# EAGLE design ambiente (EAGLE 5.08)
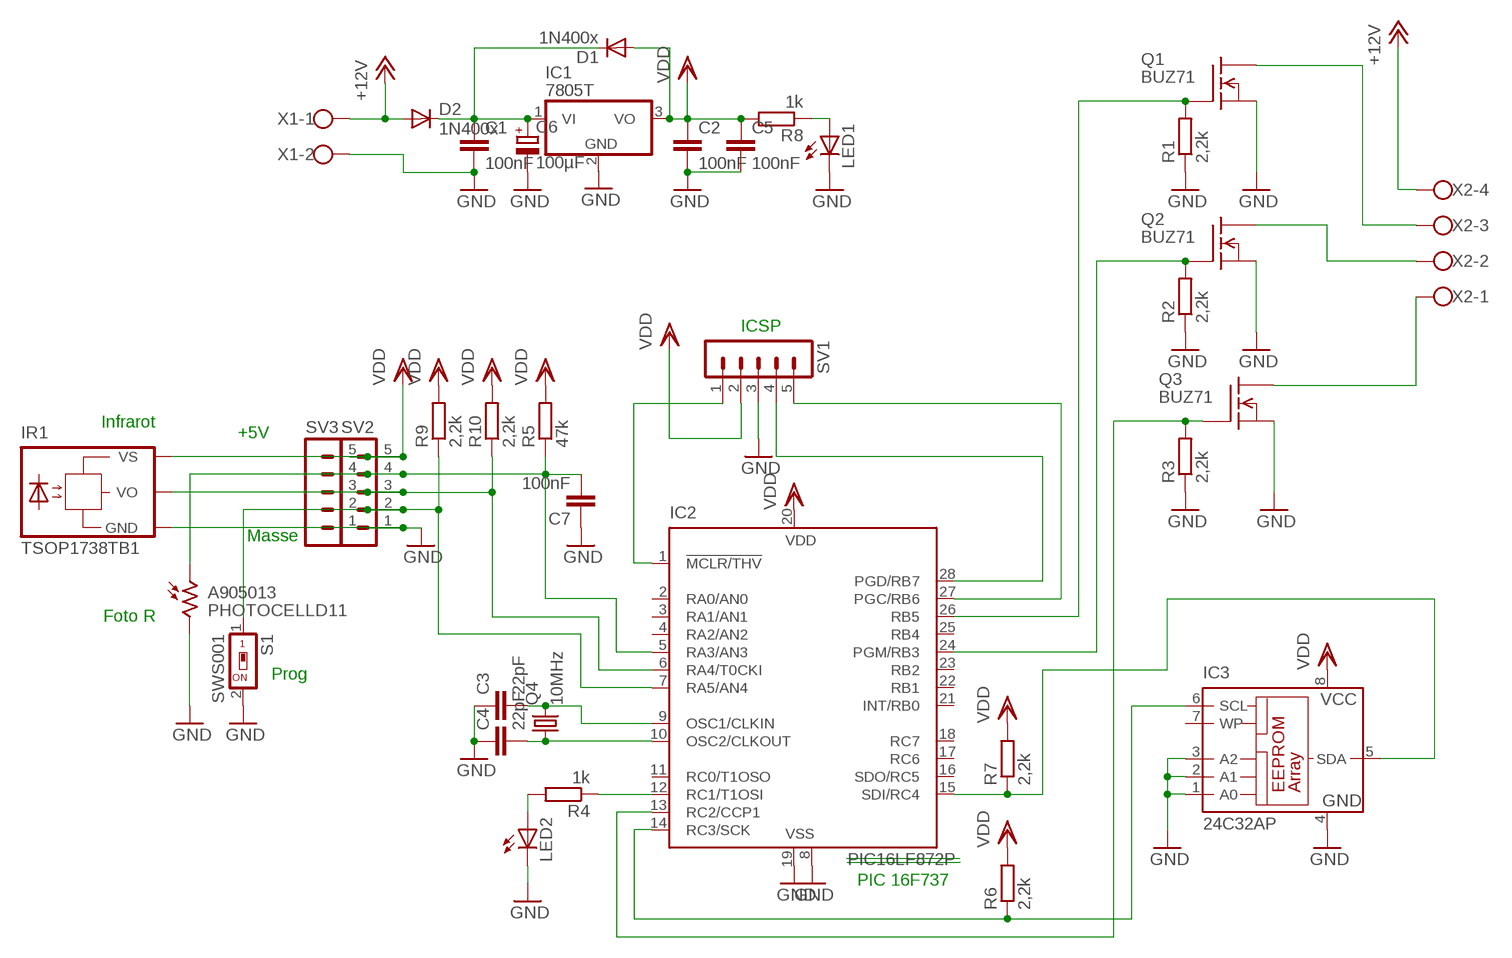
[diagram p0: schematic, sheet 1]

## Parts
A905013  PHOTOCELLD11  [D11XX_H]
C1  100nF  C-EUC1206K  [C1206K]
C2  100nF  C-EUC1206K  [C1206K]
C3  22pF  C-EUC1206K  [C1206K]
C4  22pF  C-EUC1206K  [C1206K]
C5  100nF  C-EUC1206K  [C1206K]
C6  100µF  CPOL-EUE5-10.5  [E5-10,5]
C7  100nF  C-EUC1206K  [C1206K]
D1  1N400x  DIODE-SMC  [SMC]
D2  1N400x  DIODE-SMC  [SMC]
IC1  7805T  [TO220H]
IC2  PIC16LF872P  [DIL28-3]
IC3  24C32AP  [DIL8]
IR1  TSOP1738TB1  [TSOP17_TB1]
LED1  LED3MM  [LED3MM]
LED2  LED3MM  [LED3MM]
Q1  BUZ71  [TO220]
Q2  BUZ71  [TO220]
Q3  BUZ71  [TO220]
Q4  10MHz  CRYSTALHC49S  [HC49/S]
R1  2,2k  R-EU_R1206  [R1206]
R2  2,2k  R-EU_R1206  [R1206]
R3  2,2k  R-EU_R1206  [R1206]
R4  1k  R-EU_R1206  [R1206]
R5  47k  R-EU_R1206  [R1206]
R6  2,2k  R-EU_R1206  [R1206]
R7  2,2k  R-EU_R1206  [R1206]
R8  1k  R-EU_R1206  [R1206]
R9  2,2k  R-EU_R1206  [R1206]
R10  2,2k  R-EU_R1206  [R1206]
S1  SWS001  [SMS-001]
SV1  MA05-1  [MA05-1]
SV2  MA05-1  [MA05-1]
SV3  MA05-1  [MA05-1]
X1  W237-102  [W237-102]
X2  W237-4  [W237-4]

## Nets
+12V: D2.A X1.1 X2.4
GND: A905013.2 C1.2 C2.2 C3.1 C4.1 C5.2 C6.- C7.1 IC1.2(GND) IC2.8(VSS) IC2.19(VSS) IC3.1(A0) IC3.2(A1) IC3.3(A2) IC3.4(GND) IR1.GND LED1.K(C) LED2.K(C) Q1.3(S) Q2.3(S) Q3.3(S) R1.1 R2.1 R3.1 S1.2 SV1.3 SV2.1 SV3.1 X1.2
N$1: C1.1 C6.+ D1.C D2.C IC1.1(VI)
N$2: Q1.2(D) X2.3
N$3: Q2.2(D) X2.2
N$4: Q3.2(D) X2.1
N$5: IC2.13(RC2/CCP1) Q3.1(G) R3.2
N$6: IC2.24(PGM/RB3) Q2.1(G) R2.2
N$7: IC2.26(RB5) Q1.1(G) R1.2
N$8: C3.2 IC2.9(OSC1/CLKIN) Q4.2
N$9: C4.2 IC2.10(OSC2/CLKOUT) Q4.1
N$10: A905013.1 C7.2 IC2.5(RA3/AN3) R5.1 SV2.4 SV3.4
N$11: IC2.1(!MCLR/THV) SV1.1
N$12: IC2.28(PGD/RB7) SV1.4
N$13: IC2.27(PGC/RB6) SV1.5
N$14: IC2.6(RA4/T0CKI) IR1.VO R10.1 SV2.3 SV3.3
N$15: IC2.7(RA5/AN4) R9.1 S1.1 SV2.2 SV3.2
N$21: LED1.A R8.1
N$24: IC2.12(RC1/T1OSI) R4.1
N$32: IC2.14(RC3/SCK) IC3.6(SCL) R6.1
N$34: IC2.15(SDI/RC4) IC3.5(SDA) R7.1
N$35: LED2.A R4.2
VDD: C2.1 C5.1 D1.A IC1.3(VO) IC2.20(VDD) IC3.8(VCC) IR1.VS R5.2 R6.2 R7.2 R8.2 R9.2 R10.2 SV1.2 SV2.5 SV3.5
Unconnected: IC2.2(RA0/AN0) IC2.3(RA1/AN1) IC2.4(RA2/AN2) IC2.11(RC0/T1OSO) IC2.16(SDO/RC5) IC2.17(RC6) IC2.18(RC7) IC2.21(INT/RB0) IC2.22(RB1) IC2.23(RB2) IC2.25(RB4) IC3.7(WP)

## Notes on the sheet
- ICSP
- Infrarot
- +5V
- Masse
- Foto R
- Prog
- PIC 16F737

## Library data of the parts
A905013 = photo-elements:PHOTOCELL: Photo Sensor
C1-C5 C7 = rcl:C-EU: CAPACITOR, European symbol
C6 = rcl:CPOL-EU: POLARIZED CAPACITOR, European symbol
D1 D2 = diode:DIODE-: DIODE
IC1 = linear:78*: Positive VOLTAGE REGULATOR Source: http://cache.national.com/ds/LM/LM78L05.pdf http://www.fairchildsemi.com/ds/LM/LM7805.pdf
IC2 = microchip:PIC16*872: MICROCONTROLLER flash type
IC3 = microchip:24*: Serial EEPROM I2C
IR1 = telefunken:TSOP17*TB1: TSOP17..TB1 IR Receiver Modules for Remote Control Systems Source: http://www.vishay.com/docs/82042/82042.pdf
LED1 LED2 = led:LED: LED
Q1-Q3 = transistor-fet:BUZ71: N-Channel Enhancement MOSFET 50V; 14A; 0,1Ohm
Q4 = crystal:CRYSTAL: CRYSTAL
R1-R10 = rcl:R-EU_: RESISTOR, European symbol
S1 = smd-special:SWS001: SMD Dip Switch 1 pol.
SV1-SV3 = con-lstb:MA05-1: PIN HEADER
X1 = con-wago-500:W237-102: WAGO SCREW CLAMP
X2 = con-wago-500:W237-4: WAGO SCREW CLAMP

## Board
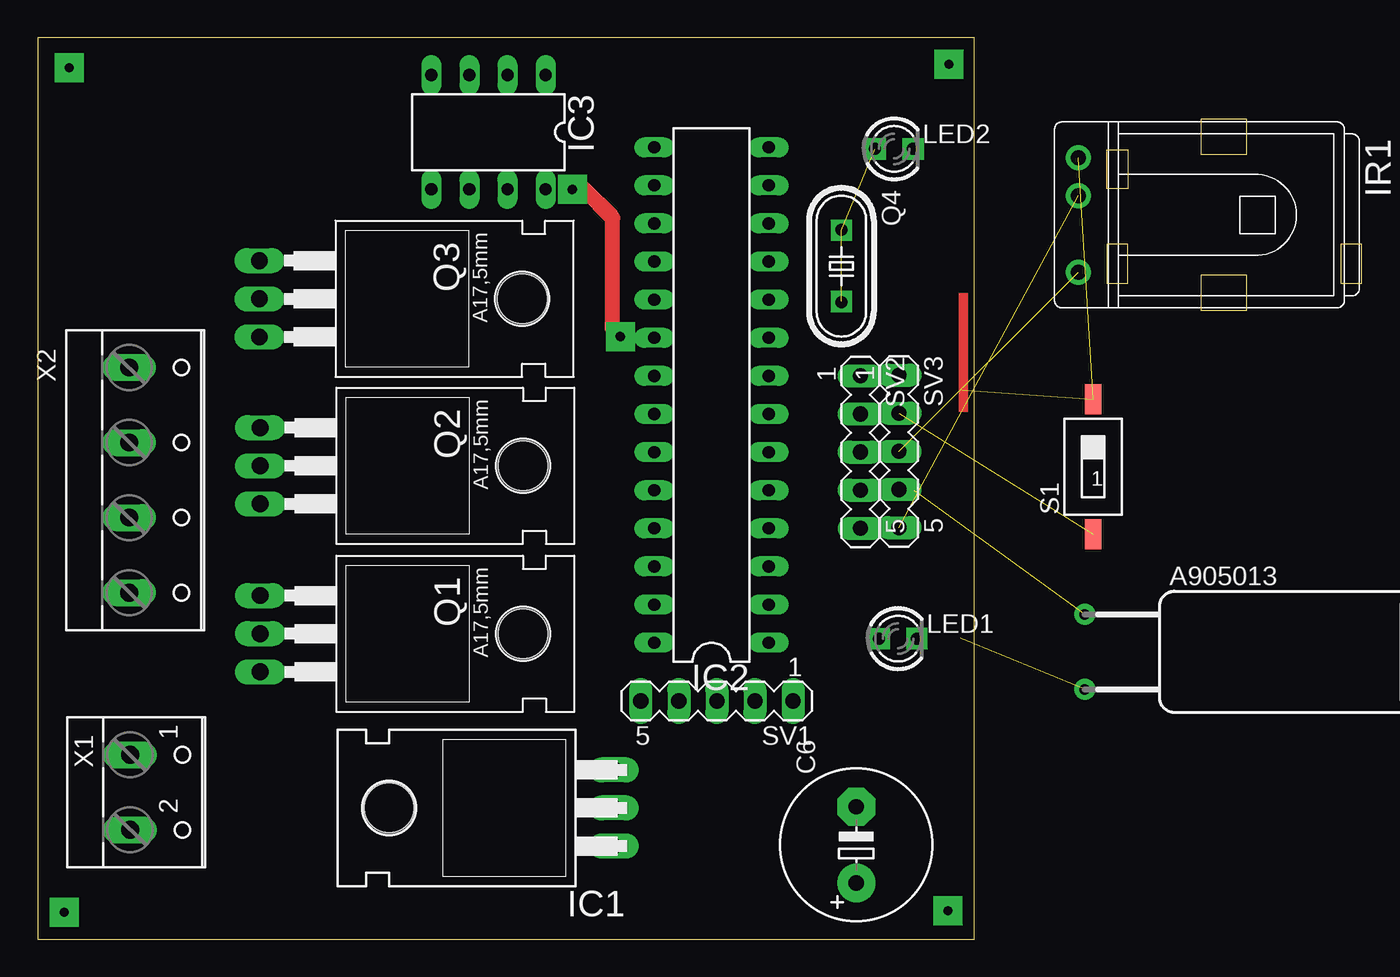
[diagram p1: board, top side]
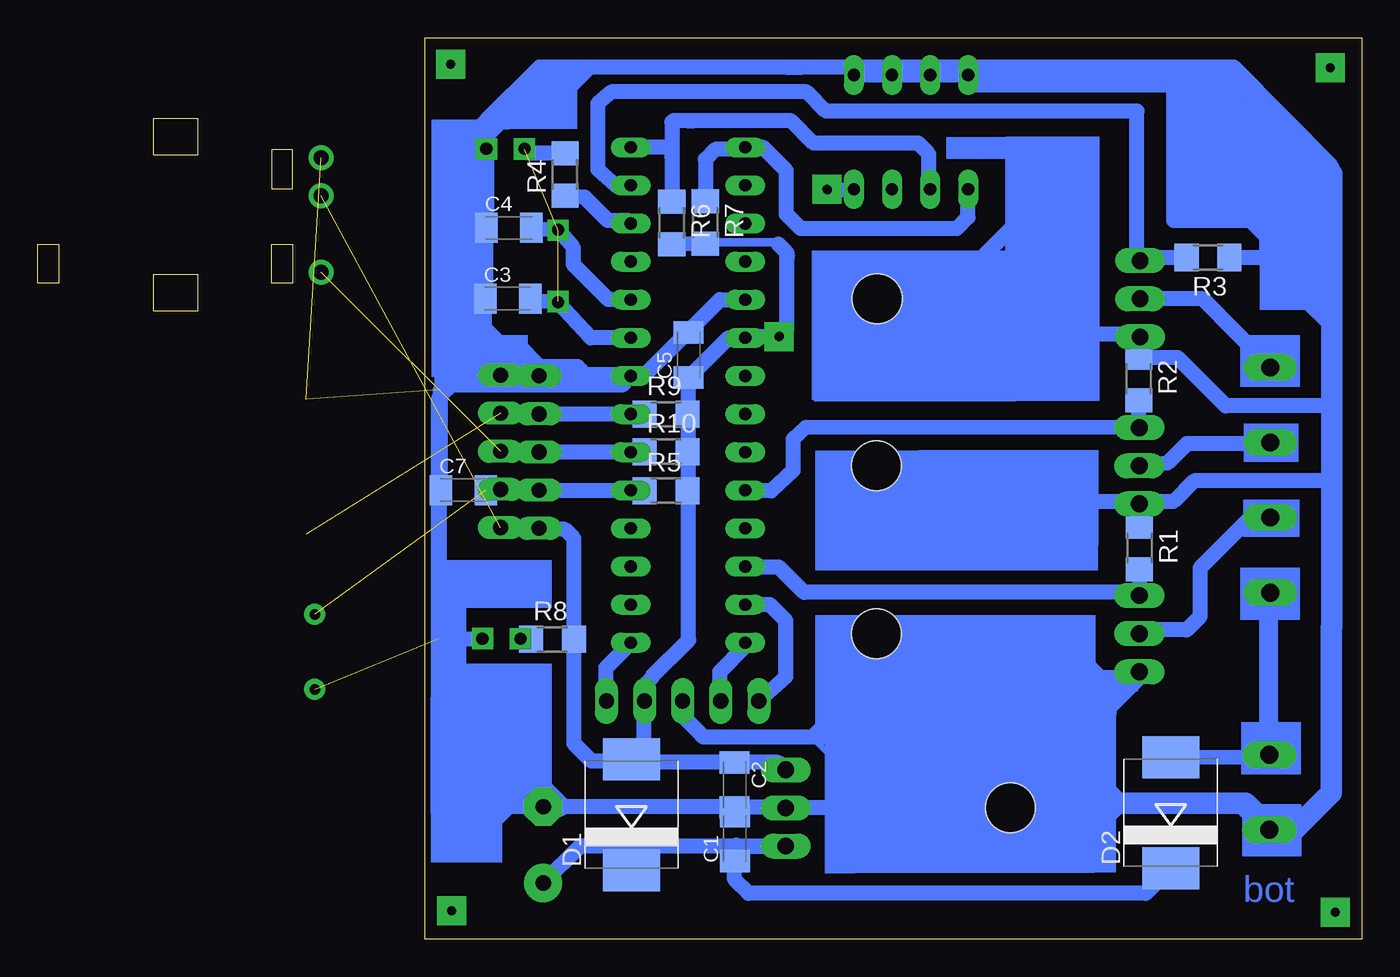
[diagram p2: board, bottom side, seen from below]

Size 88.3 x 60.09 mm. Coordinates in mm from the lower left corner, seen from the top.
Outline: 0,0 62.47,0 62.47,60.09 0,60.09 0,0
Copper layers (1*16): Top 0.035mm / dielectric 1.5mm / Bottom 0.035mm
Design rules "default": minimum track width 10mil, minimum drill 24mil, track to track 8mil, track to pad 8mil, pad to pad 8mil, via to via 8mil, smd to smd 8mil, copper to edge 40mil, drill to drill 8mil, minimum pad ring 10mil, minimum via ring 8mil, stop-mask expansion 4mil, vias tented up to drill 0mil, thermal gap 10mil

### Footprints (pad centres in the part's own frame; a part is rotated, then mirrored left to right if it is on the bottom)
D11XX_H = drill 0.7 pad 1.4 round: 1 -2.5,-5; 2 2.5,-5
C1206K = smd 1.5 x 2: 1 -1.5,0; 2 1.5,0
E5-10,5 = drill 1.016 pad 2.54 round: + -2.54,0 | drill 1.016 pad 2.54 octagon: - 2.54,0
SMC = smd 2.8 x 3.8: A 3.7,0; C -3.7,0
TO220H = drill 1.118 long: 1 -2.54,-10.16; 2 0,-10.16; 3 2.54,-10.16 | hole 3.302: 0,4.826
DIL28-3 = drill 0.813 long: 1 -16.51,-3.81; 2 -13.97,-3.81; 3 -11.43,-3.81; 4 -8.89,-3.81; 5 -6.35,-3.81; 6 -3.81,-3.81; 7 -1.27,-3.81; 8 1.27,-3.81; 9 3.81,-3.81; 10 6.35,-3.81; 11 8.89,-3.81; 12 11.43,-3.81; 13 13.97,-3.81; 14 16.51,-3.81; 15 16.51,3.81; 16 13.97,3.81; 17 11.43,3.81; 18 8.89,3.81; 19 6.35,3.81; 20 3.81,3.81; 21 1.27,3.81; 22 -1.27,3.81; 23 -3.81,3.81; 24 -6.35,3.81; 25 -8.89,3.81; 26 -11.43,3.81; 27 -13.97,3.81; 28 -16.51,3.81
DIL8 = drill 0.813 long: 1 -3.81,-3.81; 2 -1.27,-3.81; 3 1.27,-3.81; 4 3.81,-3.81; 5 3.81,3.81; 6 1.27,3.81; 7 -1.27,3.81; 8 -3.81,3.81
TSOP17_TB1 = drill 1 pad 1.676 round: GND 0,-3.81; VO 0,3.81; VS 0,-1.27
LED3MM = drill 0.813 octagon: A -1.27,0; K 1.27,0
TO220 = drill 1.118 long: 1 -2.54,-6.35; 2 0,-6.35; 3 2.54,-6.35 | hole 3.302: 0,11.176
HC49/S = drill 0.813 round: 1 -2.413,0; 2 2.413,0
R1206 = smd 1.6 x 1.803: 1 -1.422,0; 2 1.422,0
SMS-001 = smd 1.092 x 2.007: 1 0,-4.496; 2 0,4.496
MA05-1 = drill 1.016 long: 1 -5.08,0; 2 -2.54,0; 3 0,0; 4 2.54,0; 5 5.08,0
W237-102 = drill 1.194 long: 1 -2.5,-1.27; 2 2.5,-1.27
W237-4 = drill 1.194 long: 1 -7.5,-1.27; 2 -2.5,-1.27; 3 2.5,-1.27; 4 7.5,-1.27

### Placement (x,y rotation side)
A905013  74.82,19.14 270 top
C1  41.81,6.7 90 bottom
C2  41.82,10.28 270 bottom
C3  56.94,42.69 0 bottom
C4  56.87,47.41 0 bottom
C5  44.9,38.93 90 bottom
C6  54.59,6.28 90 top
C7  59.92,29.93 0 bottom
D1  48.7,8.28 90 bottom
D2  12.76,8.41 90 bottom
IC1  28.27,8.74 90 top
IC2  44.93,36.26 90 top
IC3  30.06,53.78 180 top
IR1  69.4,48.27 180 top
LED1  57.38,20.03 0 top
LED2  57.11,52.67 0 top
Q1  21.19,20.36 270 top
Q2  21.19,31.55 270 top
Q3  21.14,42.68 270 top
Q4  53.6,44.86 270 top
R1  14.83,26.06 270 bottom
R2  14.89,37.33 270 bottom
R3  10.27,45.43 180 bottom
R4  53.14,50.96 90 bottom
R5  46.4,29.9 0 bottom
R6  46.02,47.74 270 bottom
R7  43.78,47.76 270 bottom
R8  53.97,19.98 0 bottom
R9  46.4,34.98 0 bottom
R10  46.4,32.49 0 bottom
S1  70.38,31.47 0 top
SV1  45.29,15.87 180 top
SV2  54.87,32.46 270 top
SV3  57.43,32.51 270 top
X1  7.44,9.79 270 top
X2  7.38,30.6 270 top

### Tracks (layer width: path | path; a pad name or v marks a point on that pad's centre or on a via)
+12V
  Bottom 1.016: X2.4 6.15,23.06 6.15,12.3 X1.1 7.38,12.09 D2.A
GND  (3 unrouted)
  Bottom 0.406: SV3.1 57.91,37.59 57.91,36.93
  Bottom 0.813: C5.2 44.9,40.53 44.84,40.59 | IC2.8 49.34,36.93 53.62,36.93 57.91,36.93 58.44,36.93 C3.1
  Bottom 1.016: C2.2 38.47,8.78 IC1.2 33.1,8.74 31.27,10.57 | 31.27,10.57 28.38,13.46 21.84,13.46 18.8,10.42 | 2.03,35.54 2.03,30.53 11.21,30.53 12.59,29.15 14.81,29.15 | 2.03,45.69 2.03,35.54 | 2.03,50.11 2.03,45.69 | 2.03,50.11 2.03,51.01 2.03,51.51 8.55,58.11 10.84,58.11 | 10.84,58.11 33.88,58.11 | 38.41,58.11 54.85,58.11 58.38,54.57 LED2.K C4.1 58.44,47.17 C3.1 | 2.03,50.11 2.04,50.12 | 38.41,58.11 37.4,58.09 | IC2.19 42.81,42.61 44.84,40.59 47.77,37.65 48.63,37.65 IC2.8 48.86,37.65 | SV2.1 53.57,36.98 53.62,36.93 | 10.84,58.11 10.68,57.94 | 45.33,8.82 41.75,8.82 C2.2 | 45.33,8.82 C6.- | 45.33,8.82 45.33,8.83 | C2.2 41.71,7.96 C1.2 | IC3.4 IC3.3 IC3.2 IC3.1 33.83,58.06 33.88,58.11 | 61.6,29.47 C7.1 | 61.6,29.47 61.6,29.53 61.45,29.67 61.45,36.6 60.96,37.1 SV3.1 | 14.81,29.15 Q2.3 | 14.81,29.15 14.81,27.5 R1.1 | Q3.3 14.79,38.84 R2.1 12.3,38.75 9.08,35.54 2.03,35.54 | 33.88,58.11 38.41,58.11 | R3.1 5.09,45.42 2.03,45.69 | 17.94,8.92 18.01,9.04 18.8,10.42 | 18.8,10.42 18.31,10.91 18.31,13.95 14.84,17.42 Q1.3 | SV1.3 45.29,14.88 44.06,13.65 44.06,13.61 43.91,13.46 34.17,13.46 31.27,10.57 | 7.79,8.89 6.17,7.61 X1.2 6.14,7.32 4.49,7.32 | LED1.K 61.47,20.03 61.51,20.07 61.51,29.39 61.6,29.47
  Bottom 1.422: 7.79,8.89 6.19,7.29 5.98,7.29 7.73,9.04 18.01,9.04 | 4.49,7.32 2.04,9.76 2.04,20.79 2.03,20.8 2.03,51.01
N$1
  Bottom 1.016: 48.66,6.2 IC1.1 41.65,6.2 41.72,6.27 41.72,4.96 C1.1 41.83,3.97 40.9,3.05 14.43,3.05 D2.C | 48.66,6.2 52.13,6.2 C6.+ 54.41,3.74 | D1.C 48.66,4.62 48.66,6.2
N$2
  Bottom 1.016: X2.3 7.44,28.1 10.79,24.74 10.79,21.5 11.69,20.6 14.77,20.6 Q1.2
N$3
  Bottom 1.016: Q2.2 12.99,31.72 11.69,33.02 6.19,33.02 X2.2
N$4
  Bottom 1.016: Q3.2 10.63,42.67 X2.1
N$5
  Bottom 1.016: IC2.13 48.77,50.21 49.73,50.21 50.96,51.3 50.96,55.69 50.05,56.47 37.01,56.47 35.72,55.18 15,55.18 15,45.6 Q3.1 14.49,45.42 R3.2
N$6
  Bottom 1.016: R2.2 14.89,34.31 Q2.1 37.09,34.11 37.93,33.32 37.93,31.22 39.37,29.87 41.08,29.87 IC2.24
N$7
  Bottom 1.016: Q1.1 14.83,23.08 R1.2 14.83,23.16 14.88,23.11 37.2,23.11 38.88,24.79 41.08,24.79 IC2.26
N$8
  Bottom 1.016: IC2.9 51.41,40.07 Q4.2 55.38,42.55 C3.2
N$9
  Bottom 1.016: IC2.10 50.24,42.61 52.57,44.95 52.57,46.07 Q4.1 55.47,47.31 C4.2
N$10  (1 unrouted)
  Bottom 0.406: IC2.5 47.82,29.91 R5.1
  Bottom 1.016: C7.2 58.4,29.97 SV3.4 57.38,29.92 SV2.4 54.86,29.94 54.82,29.9 R5.1
N$11
  Bottom 1.016: SV1.1 50.41,18.09 IC2.1
N$12
  Bottom 1.016: IC2.28 41.12,19.51 42.8,17.83 42.8,15.66 SV1.4
N$13
  Bottom 1.016: IC2.27 39.48,22.29 38.41,21.23 38.41,17.48 SV1.5
N$14  (1 unrouted)
  Bottom 0.406: IC2.6 47.82,32.45 R10.1
  Bottom 1.016: IC2.6 SV2.3 57.38,32.46 SV3.3
N$15  (1 unrouted)
  Bottom 0.406: R9.1 47.88,34.98 47.88,35.01 IC2.7
  Bottom 1.016: IC2.7 SV2.2 57.38,35 SV3.2
N$16
  Bottom 1.016: 58.57,37.12 60.54,37.12 61.56,36.1 61.56,15.61 54.68,8.73
N$17
  Bottom 1.016: 52.22,57.78 53.24,56.62 53.24,56.29
N$18
  Bottom 1.016: 10.91,55.2 13.8,58.09 15.11,58.09
N$19
  Bottom 1.016: 25.8,44.95 22.91,47.84 22.91,48.37
N$20
  Bottom 1.016: 54.64,8.83 57.4,8.83
N$21
  Bottom 1.016: LED1.A 55.44,20.03 R8.1
N$22
  Bottom 1.016: 8.48,57.11 2.61,51.24 | 8.48,57.11 8.74,57.37 | 8.48,57.11 8.48,51.5 8.1,51.88 3.64,51.88 7.13,55.37 8.16,55.37 7.84,55.05 7.84,52.46 7.71,52.59 5.06,52.59 6.87,54.4 7.58,54.4 6.61,53.43 6.61,52.92 6.87,53.17 7.32,53.17
N$23
  Bottom 1.016: 12.1,58.08 12.55,57.63 12.55,47.88 6.29,47.88 6.35,47.82 6.35,46.01 6.1,46.27 2.67,46.27 2.67,47.49 3.06,47.11 5.64,47.11
N$24
  Bottom 1.016: IC2.12 48.94,47.89 50.27,47.89 51.83,49.44 R4.1
N$25
  Bottom 1.27: 6.21,12.46 6.21,23.16
N$26
  Bottom 1.016: 14.69,40.4 14.77,40.32 18.89,40.32
N$27
  Bottom 1.422: 2.1,41.25 3.43,42.59 3.43,42.68 5.51,44.76 5.51,46.28 7.77,48.54 7.8,48.54
N$28  (via drill 0.6 pad 1.93)
  other vias: 2.11,58.09
N$29  (via drill 0.6 pad 1.93)
  Top 1.016: v35.66,49.99 35.7,50.02 36.43,50.02 38.32,48.13 38.32,40.7 v38.86,40.16
N$30  (via drill 0.6 pad 1.93)
  other vias: 60.69,1.88
N$31  (via drill 0.6 pad 1.93)
  other vias: 1.78,1.8
N$32
  Bottom 1.016: IC3.6 28.88,50.06 28.88,52.34 29.59,53.05 36.56,53.05 38.04,54.53 44.63,54.53 | 44.63,54.53 44.89,54.53 | R6.1 46.02,52.15 46.01,52.15 46.01,52.77 | 46.01,52.77 46.01,54.47 45.96,54.53 44.63,54.53 | IC2.14 48.74,52.77 46.01,52.77
N$33
  Bottom 1.016: 14.84,29.14 18.66,29.14
N$34
  Bottom 1.016: IC3.5 26.26,48.09 27.01,47.35 37.42,47.35 38.38,48.31 38.38,51.22 39.93,52.77 IC2.15 41.26,52.64 43.13,52.64 43.78,51.99 R7.1
N$35
  Bottom 1.016: 53.22,52.47 R4.2 55.56,52.38 LED2.A
N$36
  Bottom 1.016: 16.86,15.06 18.44,16.64 18.44,17.25
N$37  (via drill 0.6 pad 1.93)
  other vias: 60.76,58.3
N$38
  Bottom 1.016: 56.92,15.02 57.13,14.8 60.28,14.8 57.49,12.01 57.13,12.01 57.13,14.06 58.72,14.06 57.73,13.07 57.66,13.07
N$39
  Bottom 1.016: 54.69,8.87 54.73,8.9 54.73,10.92
N$40
  Bottom 1.422: 55.87,56.35 59.46,52.76 59.46,52.1
N$41
  Bottom 1.422: 58.9,40.81 57.71,39.62 57.68,39.62
N$42
  Bottom 1.422: 56.16,39.11 54.85,37.8 54.41,37.8
N$43
  Bottom 1.422: 60.12,23.18 61.1,22.2 61.1,20.36
N$44
  Bottom 1.422: 60.44,22.88 60.44,17.5 60.53,17.41
N$45
  Bottom 1.422: 58.72,6.15 58.72,7.31 57.02,9
N$46
  Bottom 1.422: 55.69,11.94 55.69,10.99 53.55,8.85
N$47
  Bottom 1.422: 17.61,12.15 17.61,10.34 16.48,9.21
N$48
  Bottom 1.422: 17.2,7.66 17.2,8.2 16.57,8.82
N$49
  Bottom 1.016: 11.51,57.68 27.03,57.68 27.03,58.07
N$50
  Bottom 1.016: 52.01,58.09 51.54,58.07 54.08,55.53
N$51  (via drill 0.6 pad 1.42)  (2 unrouted)
  other vias: 55.84,52.66 53.59,47.25 55.84,52.66 53.59,42.5
N$52  (via drill 0.6 pad 1.42)
  other vias: 58.38,52.66
N$53  (via drill 0.6 pad 1.42)
  other vias: 56.11,20.02
N$54  (via drill 0.6 pad 1.42)
  other vias: 58.63,20.03
N$55
  Bottom 0.406: 36.49,13.44 36.49,13.27 35.24,12.02
N$56
  Bottom 0.406: 37.15,13.52 36.99,13.52 35.32,15.19
N$57
  Bottom 0.406: 17.02,17.43 18.35,18.77
N$58
  Bottom 1.016: 5.64,47.03 5.64,48.23 5.67,48.26
N$59
  Bottom 1.016: 38.32,45.4 38.37,45.77 38.93,46.33
N$60
  Bottom 1.016: 57.63,55.18 57.75,55.18 59.11,53.83
N$61
  Bottom 1.016: 56.29,39.68 56.29,39.66 54.79,38.16 52.29,38.16 52.01,37.88
N$62
  Bottom 1.016: 49.07,37.19 49.33,36.92 60.55,36.92
VDD  (via drill 0.6)  (1 unrouted)
  Top 1.016: v35.64,49.94 36.46,49.94 38.34,48.06 38.34,40.67 v38.84,40.18
  Bottom 0.406: R9.2 44.9,34.98 44.9,35.03 | R10.2 44.9,32.49 44.9,32.44
  Bottom 0.61: R7.2 43.9,46.33 43.9,46.42 39.01,46.44 38.34,45.69
  Bottom 1.016: 44.9,29.98 44.9,19.93 47.36,17.47 47.36,17.41 47.74,17.03 47.74,15.78 SV1.2 47.87,15.64 47.87,11.99 47.99,11.86 | 48.58,11.86 51.37,11.86 52.53,13.02 52.53,20.03 52.55,20.02 R8.2 52.55,26.71 53.15,27.31 54.8,27.31 SV2.5 54.87,27.43 SV3.5 | 48.45,11.73 D1.A 48.58,11.86 | IC3.8 33.9,49.94 v35.64,49.94 | R6.2 43.8,46.35 R7.2 | 38.34,45.69 38.34,40.67 v38.84,40.18 41.02,40.18 IC2.20 42.25,40.07 C5.1 44.9,35.03 44.9,32.44 44.9,29.98 | 47.99,11.86 47.92,11.78 C2.1 38.93,11.78 IC1.3 | 47.99,11.86 48.58,11.86 | 44.9,29.98 R5.2
(copper drawn outside any net)
  shapes: Bottom area x41, Top area x1

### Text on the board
Bottom: bot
